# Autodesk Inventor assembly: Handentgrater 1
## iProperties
Created: 2006-12
Part Number: Handentgrater 1
Document SubType Name: Assembly
Designer: Kumpf
Manufacturer: Standard
Standards Organization: Custom
Author: Kumpf
